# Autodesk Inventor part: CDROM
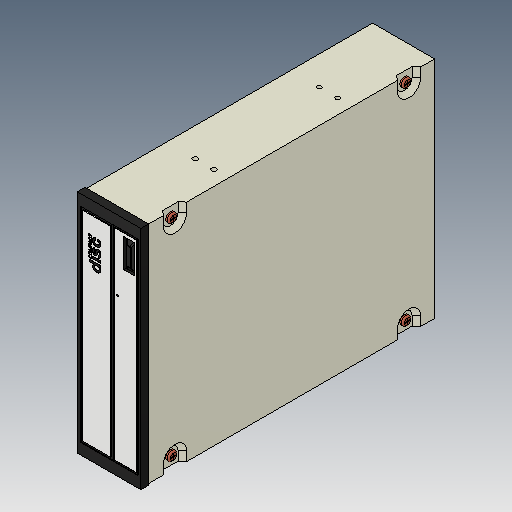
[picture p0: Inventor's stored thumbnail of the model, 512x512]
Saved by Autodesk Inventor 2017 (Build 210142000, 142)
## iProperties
Created: 2005-12
Part Number: CDROM
Material: Generic
Document SubType Name: Modeling
Designer: DanielSeverino
Density: 1 g/cm^3
Appearance: Default
Author: DanielSeverino
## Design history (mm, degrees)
feature "Solid1"
body "Solid2"
